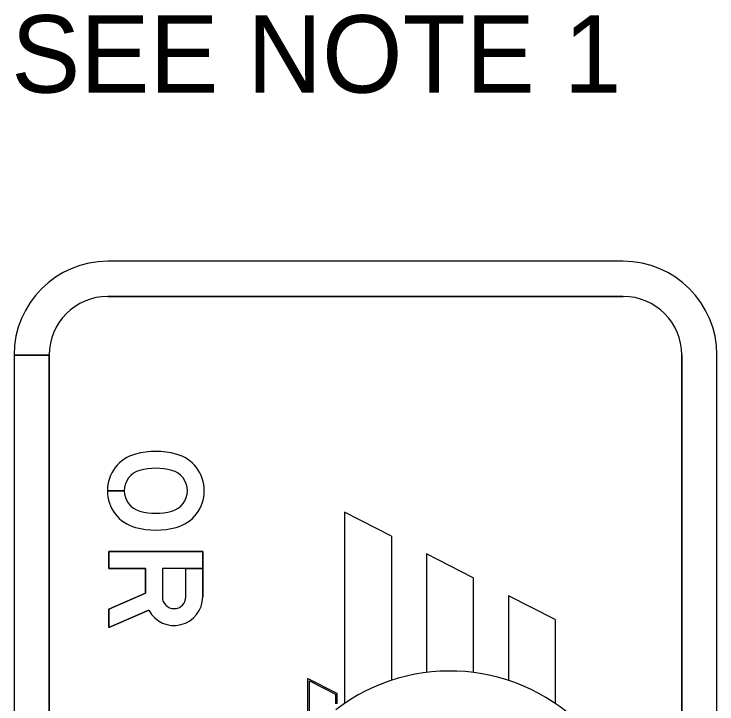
# Model space of a CAD drawing. Extents: x 46672 to 47298, y 5424 to 5742.
# Drawn here: x 47192.11 to 47217.52, y 5716.74 to 5741.69 of the extents above; entities that cross this region are included whole.
import ezdxf

# ---------------------------------------------------------------- set-up
doc = ezdxf.new("R2010")
doc.units = 0
doc.layers.add('SheetBorder_dp', color=7, linetype='Continuous')
doc.layers.add('TextNotes', color=7, linetype='Continuous')

msp = doc.modelspace()

# ---------------------------------------------------------------- linework, layer by layer
at = {"layer": 'TextNotes'}
for p, q in [((47214.133, 5732.75), (47195.498, 5732.75)), ((47214.133, 5732.75), (47195.498, 5732.75)), ((47214.133, 5732.75), (47195.498, 5732.75)), ((47214.133, 5731.48), (47195.498, 5731.48)), ((47195.498, 5731.48), (47214.133, 5731.48)), ((47195.498, 5731.48), (47214.133, 5731.48)), ((47192.11, 5729.362), (47192.11, 5675.152)), ((47192.11, 5729.362), (47192.11, 5675.152)), ((47192.11, 5729.362), (47193.381, 5729.362)), ((47192.11, 5729.362), (47193.381, 5729.362)), ((47192.11, 5729.362), (47192.237, 5729.362)), ((47192.237, 5729.361), (47192.11, 5729.361)), ((47192.11, 5729.349), (47192.11, 5675.152)), ((47193.381, 5729.349), (47192.11, 5729.349)), ((47192.11, 5729.349), (47192.11, 5675.152)), ((47193.381, 5729.349), (47192.11, 5729.349)), ((47193.381, 5729.362), (47193.381, 5675.152)), ((47193.381, 5675.152), (47193.381, 5729.349)), ((47193.381, 5675.152), (47193.381, 5729.349)), ((47216.251, 5675.152), (47216.251, 5729.362)), ((47216.251, 5729.362), (47216.251, 5675.152)), ((47216.251, 5729.362), (47216.251, 5675.152)), ((47217.521, 5675.152), (47217.521, 5729.362)), ((47217.521, 5675.152), (47217.521, 5729.362)), ((47217.521, 5675.152), (47217.521, 5729.362)), ((47217.521, 5675.152), (47217.521, 5729.362)), ((47196.093, 5724.453), (47195.483, 5724.453)), ((47196.093, 5724.453), (47195.483, 5724.453)), ((47195.483, 5724.452), (47196.093, 5724.452)), ((47195.483, 5724.452), (47196.093, 5724.452)), ((47204.056, 5723.674), (47204.056, 5716.758)), ((47205.75, 5722.812), (47204.056, 5723.674)), ((47205.75, 5722.812), (47205.75, 5717.592)), ((47207.02, 5722.166), (47207.02, 5717.88)), ((47208.714, 5721.303), (47207.02, 5722.166)), ((47208.714, 5721.303), (47208.714, 5717.88)), ((47209.984, 5720.657), (47209.984, 5717.592)), ((47211.677, 5719.795), (47209.984, 5720.657)), ((47211.677, 5719.795), (47211.677, 5716.758)), ((47202.73, 5717.668), (47203.784, 5717.131)), ((47202.73, 5716.436), (47202.73, 5717.668)), ((47202.786, 5717.577), (47203.729, 5717.097)), ((47202.786, 5709.11), (47202.786, 5717.577)), ((47203.729, 5717.097), (47203.729, 5716.742)), ((47203.784, 5717.131), (47203.784, 5716.742))]:
    msp.add_line(p, q, dxfattribs=at)
for points in [[(47198.93, 5720.612), (47198.93, 5722.25), (47195.542, 5722.25), (47195.542, 5721.64), (47196.863, 5721.64), (47196.863, 5720.743), (47195.542, 5720.17), (47195.542, 5719.506), (47196.983, 5720.13)], [(47196.983, 5720.13), (47195.542, 5719.506), (47195.542, 5720.17), (47196.863, 5720.743), (47196.863, 5721.64), (47195.542, 5721.64), (47195.542, 5722.25), (47198.93, 5722.25), (47198.93, 5721.641), (47197.473, 5721.64), (47197.473, 5720.612)], [(47196.983, 5720.13), (47195.542, 5719.506), (47195.542, 5720.17), (47196.863, 5720.743), (47196.863, 5721.64), (47195.542, 5721.64), (47195.542, 5722.25), (47198.93, 5722.25), (47198.93, 5721.641), (47197.473, 5721.64), (47197.473, 5720.612)], [(47198.32, 5720.612), (47198.32, 5721.64), (47197.473, 5721.64), (47197.473, 5720.612)], [(47198.32, 5721.64), (47198.93, 5721.64), (47198.93, 5720.612)], [(47198.32, 5720.612), (47198.32, 5721.64)], [(47198.32, 5721.64), (47198.93, 5721.64), (47198.93, 5720.612)], [(47198.32, 5720.612), (47198.32, 5721.64)]]:
    msp.add_lwpolyline(points, dxfattribs=at)
for centre, radius, start, end in [((47195.498, 5729.362), 3.388, 90, 180), ((47195.498, 5729.362), 3.388, 90, 180), ((47195.498, 5729.362), 3.388, 90, 180), ((47214.133, 5729.362), 3.388, 360, 90), ((47214.133, 5729.362), 3.388, 360, 90), ((47214.133, 5729.362), 3.388, 360, 90), ((47195.498, 5729.362), 2.118, 90, 180), ((47195.498, 5729.362), 2.118, 90, 180), ((47195.498, 5729.362), 2.118, 90, 180), ((47214.133, 5729.362), 2.118, 360, 90), ((47214.133, 5729.362), 2.118, 360, 90), ((47214.133, 5729.362), 2.118, 360, 90), ((47197.236, 5723.03), 2.846, 75.0382, 104.9618), ((47197.236, 5723.03), 2.846, 75.0382, 104.9618), ((47197.236, 5723.03), 2.846, 75.0382, 104.9618), ((47196.856, 5724.453), 1.373, 104.9618, 255.0382), ((47196.856, 5724.453), 1.373, 104.9618, 180), ((47196.856, 5724.453), 1.373, 104.9618, 180), ((47197.616, 5724.453), 1.373, 284.9618, 75.0382), ((47197.616, 5724.453), 1.373, 284.9618, 75.0382), ((47197.616, 5724.453), 1.373, 284.9618, 75.0382), ((47196.856, 5724.453), 0.763, 104.9618, 255.0382), ((47196.856, 5724.453), 0.763, 104.9618, 180), ((47196.856, 5724.453), 0.763, 104.9618, 180), ((47197.236, 5723.03), 2.236, 75.0382, 104.9618), ((47197.236, 5723.03), 2.236, 75.0382, 104.9618), ((47197.236, 5723.03), 2.236, 75.0382, 104.9618), ((47197.616, 5724.453), 0.763, 284.9618, 75.0382), ((47197.616, 5724.453), 0.763, 284.9618, 75.0382), ((47197.616, 5724.453), 0.763, 284.9618, 75.0382), ((47196.856, 5724.453), 1.373, 180.0071, 255.0382), ((47196.856, 5724.453), 1.373, 180.0071, 255.0382), ((47196.856, 5724.453), 0.763, 180.0127, 255.0382), ((47196.856, 5724.453), 0.763, 180.0127, 255.0382), ((47197.236, 5725.876), 2.236, 255.0382, 284.9618), ((47197.236, 5725.876), 2.236, 255.0382, 284.9618), ((47197.236, 5725.876), 2.236, 255.0382, 284.9618), ((47197.236, 5725.876), 2.846, 255.0382, 284.9618), ((47197.236, 5725.876), 2.846, 255.0382, 284.9618), ((47197.236, 5725.876), 2.846, 255.0382, 284.9618), ((47197.897, 5720.612), 1.033, 207.837, 360), ((47197.897, 5720.612), 1.033, 207.837, 360), ((47197.897, 5720.612), 1.033, 207.837, 360), ((47197.897, 5720.612), 0.424, 180, 360), ((47197.897, 5720.612), 0.424, 180, 360), ((47197.897, 5720.612), 0.424, 180, 360), ((47207.866, 5711.158), 6.775, 318.5904, 127.4727)]:
    msp.add_arc(centre, radius, start, end, dxfattribs=at)

# ---------------------------------------------------------------- texts
at = {"layer": 'SheetBorder_dp'}
msp.add_text('SEE NOTE 1', height=2.8, dxfattribs=at).set_placement((47192.007, 5738.85))

doc.saveas('drawing.dxf')
